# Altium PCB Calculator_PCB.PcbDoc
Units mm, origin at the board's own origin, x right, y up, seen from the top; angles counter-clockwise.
Board outline 55 x 114 mm, 2 copper layers (Top Layer, Bottom Layer); 61 components, 55 nets, 256 pads, 33 vias.
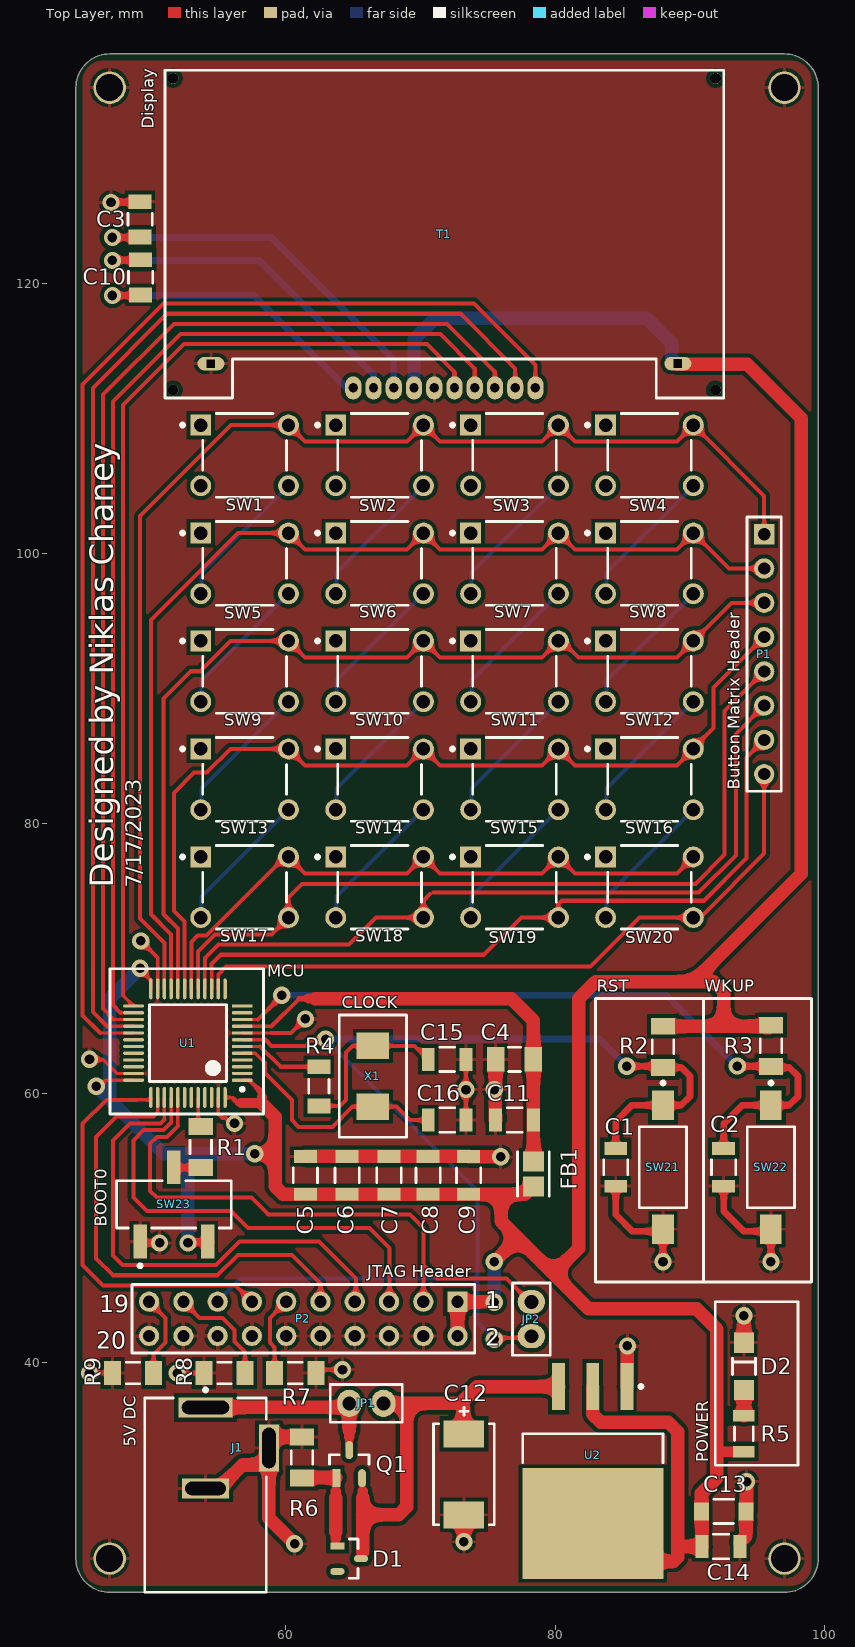
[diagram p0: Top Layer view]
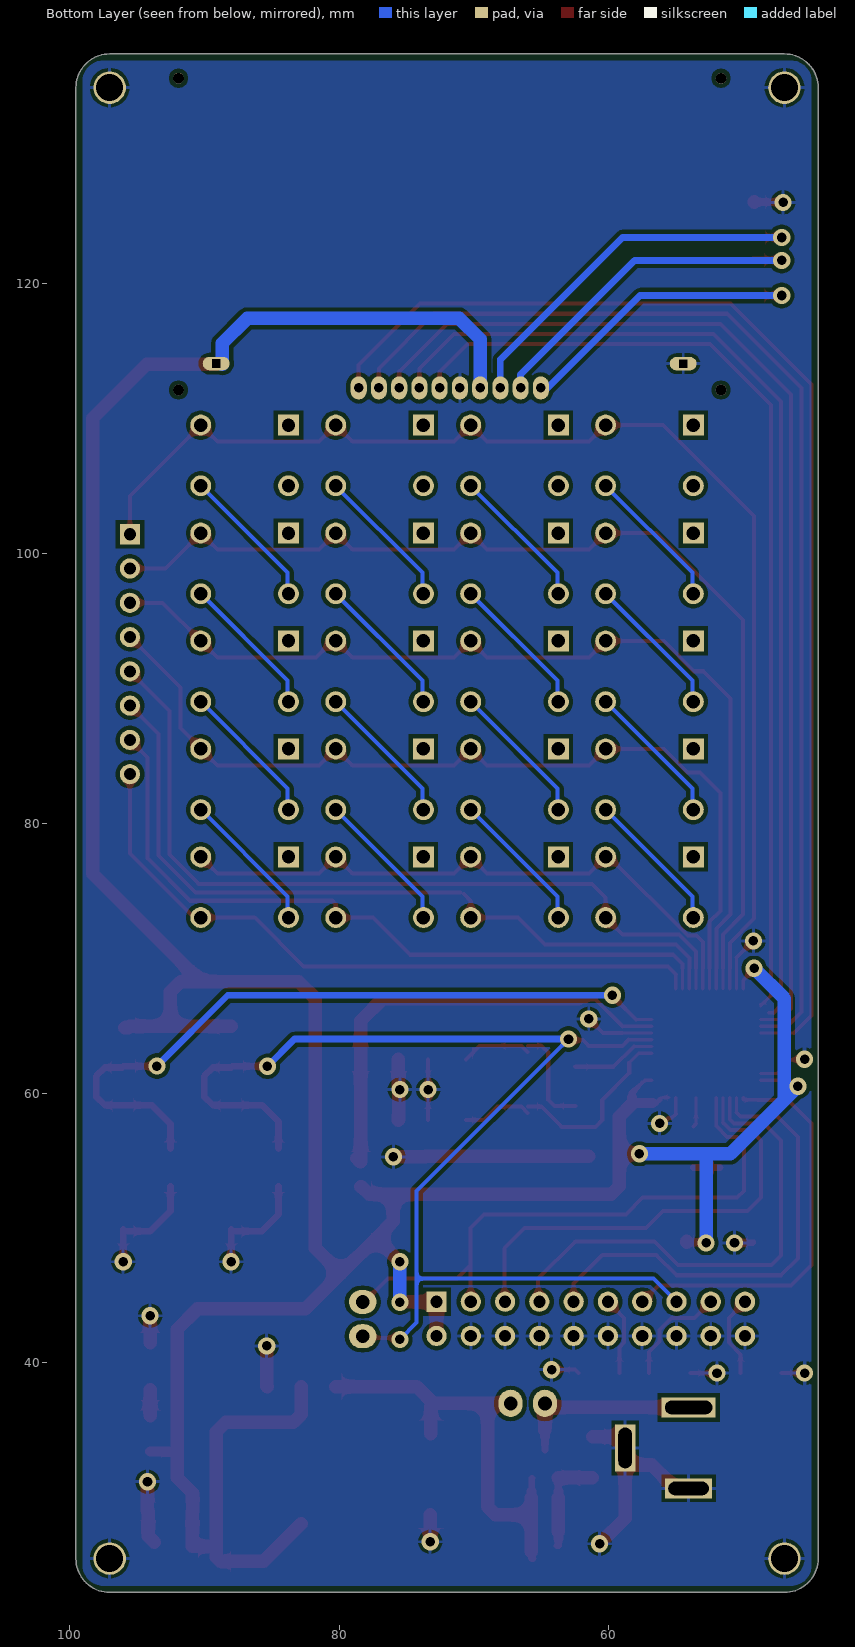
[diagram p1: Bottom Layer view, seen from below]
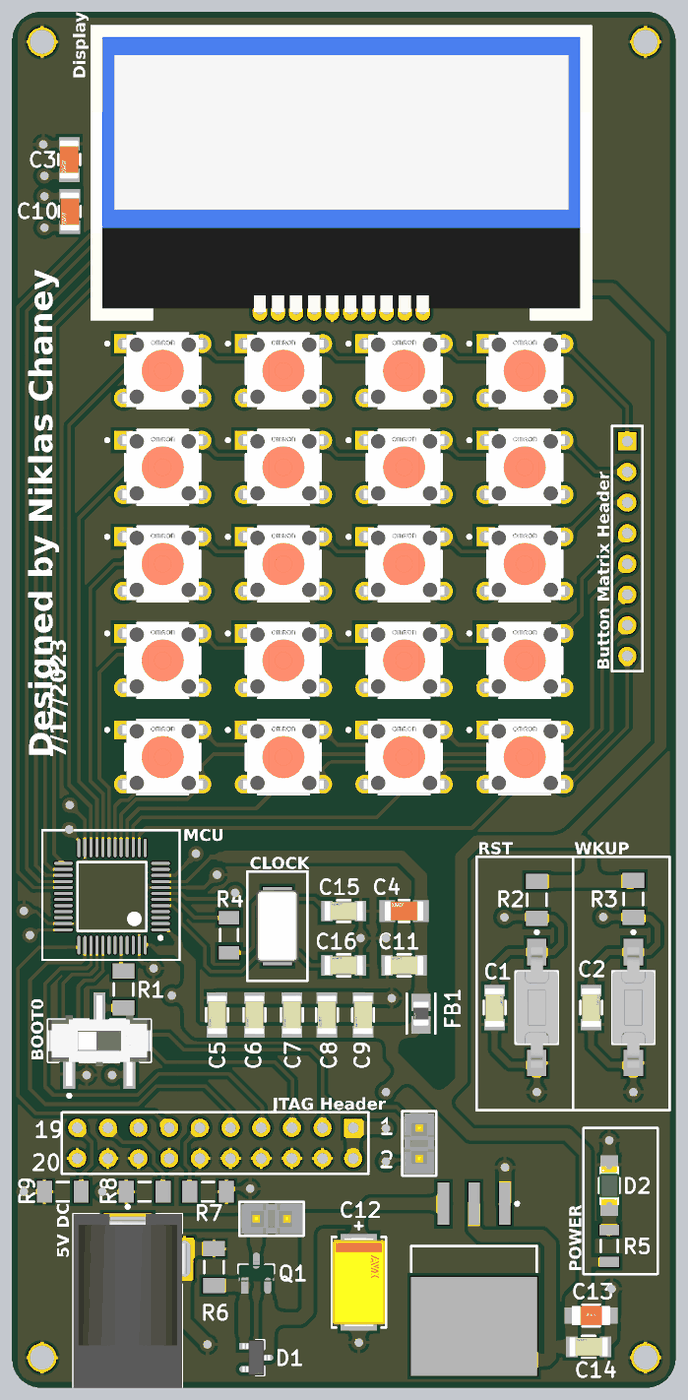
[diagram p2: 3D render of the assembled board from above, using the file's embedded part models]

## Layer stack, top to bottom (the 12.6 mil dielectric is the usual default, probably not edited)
Top Solder: solder mask 0.0102, Solder Resist, Dk 3.5
Top Layer: signal copper 0.0356
Dielectric 1: dielectric 0.32, FR-4, Dk 4.8
Bottom Layer: signal copper 0.0356
Bottom Solder: solder mask 0.0102, Solder Resist, Dk 3.5

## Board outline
44.5,25.5 ccw(c47,25.5) 47,23 97,23 ccw(c97,25.5) 99.5,25.5 99.5,134.5 ccw(c97,134.5) 97,137 47,137 ccw(c47,134.5) 44.5,134.5

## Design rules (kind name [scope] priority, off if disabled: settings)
Clearance [All] p1: gap=0.3 ignorepadtopadclearanceinfootprint=TRUE except(0.1: Arc-Arc Arc-Track Track-Track; 0.25: Arc-SMDPad Track-SMDPad)
HoleSize [All] p1: absolutevalues=TRUE maxlimit=5 minlimit=0.025 maxpercent=80.000 minpercent=20.000
MinimumSolderMaskSliver [All] p1: minsoldermaskwidth=0.046
PolygonConnect [All] p1: connectstyle=Relief reliefconductorwidth=0.254 reliefentries=4 polygonreliefangle="90 Angle" airgapwidth=0.254
RoutingVias [All] p1: holewidth=0.3 width=0.6 viastyle="Through Hole" minholewidth=0.3 minwidth=0.6 maxholewidth=0.3 maxwidth=0.6
SilkToSolderMaskClearance [IsPad] p1: minsilkscreentomaskgap=0.1 clearancetoexposedcopper=TRUE
SolderMaskExpansion [All] p1: expansion=0.102 istentingtop=FALSE
Width [All] p1: maxlimit=1 minlimit=0.25 preferedwidth=0.5
27 further rules are at their usual default settings.

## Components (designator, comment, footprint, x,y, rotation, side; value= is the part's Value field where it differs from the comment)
C1 "100nF" FP-C1206C-EB-MFG 84.5,54.5 r270 top value="0.10 μF"
C2 "100nF" FP-C1206C-EB-MFG 92.5,54.5 r270 top value="0.10 μF"
C3 "1uF" FP-1206-L_3_2_0_2-W_1_6_0-IPC_C 49.25,124.75 r270 top
C4 "10uF" FP-1206-L_3_2_0_2-W_1_6_0-IPC_B 77,62.5 r180 top
C5 "100nF" FP-C1206C-EB-MFG 61.5,53.9 r90 top value="0.10 μF"
C6 "100nF" FP-C1206C-EB-MFG 64.6,53.9 r90 top value="0.10 μF"
C7 "100nF" FP-C1206C-EB-MFG 67.7,53.9 r90 top value="0.10 μF"
C8 "100nF" FP-C1206C-EB-MFG 70.6,53.9 r90 top value="0.10 μF"
C9 "100nF" FP-C1206C-EB-MFG 73.6,53.9 r90 top value="0.10 μF"
C10 "1uF" FP-1206-L_3_2_0_2-W_1_6_0-IPC_C 49.3,120.449 r270 top
C11 "10nF" FP-C1206C-EB-MFG 77,58 r0 top value="10,000 pF"
C12 "220uF" FP-TAJE-MFG 73.25,31.75 r90 top
C13 "47uF" FP-C3216-160-0_2-MFG 92.5,29 r0 top
C14 "100nF" FP-C1206C-EB-MFG 92.3,26.4 r0 top value="0.10 μF"
C15 "20pF" FP-C1206C-EB-MFG 72,62.5 r0 top value="20 pF"
C16 "20pF" FP-C1206C-EB-MFG 72,58 r0 top value="20 pF"
D1 "BZX84-C15,215" FP-SOT23-IPC_C 64.75,25.5 r0 top
D2 "HSMG-C150" FP-HSMG-C150-MFG 94,39.75 r270 top
FB1 "BLM21AG121SN1D" FP-BLM21-0_2-t0_85-e0_5-IPC_A 78.4,54 r270 top
J1 "PJ-002A" CUI-PJ-002A_V 54.1,33.7 r270 top
JP1 "Jumper" "Jumper Small - 2.54 - GRAY" 66.02,37 r0 top
JP2 "Jumper" "Jumper Small - 2.54 - GRAY" 78.25,43.25 r270 top
P1 "Header 8" HDR1X8 95.5,101.41 r270 top
P2 "JTAG" HDR2X10 72.78,44.54 r180 top
Q1 "FDN360P" FP-527AG-IPC_B 64.75,32.5 r90 top
R1 "10K" RESC3116X65X40ML10T20 53.75,56 r270 top
R2 "10K" RESC3116X65X40ML10T20 88,63.425 r90 top
R3 "10K" RESC3116X65X40ML10T20 96,63.5 r90 top
R4 "390R" RESC3216X60X45NL10T20 62.5,60.5 r270 top
R5 "330R" RESC3116X65X40LL10T20 94,34.75 r90 top
R6 "10K" RESC3116X65X40ML10T20 61.25,33 r270 top
R7 "10K" RESC3116X65X40ML10T20 60.75,39.25 r180 top
R8 "10K" RESC3116X65X40ML10T20 55.5,39.25 r0 top
R9 "10K" RESC3116X65X40ML10T20 48.725,39.25 r0 top
SW1 "B3F-1055" FP-B3F-1055-MFG 57,107.25 r0 top
SW2 "B3F-1055" FP-B3F-1055-MFG 67,107.25 r0 top
SW3 "B3F-1055" FP-B3F-1055-MFG 77,107.25 r0 top
SW4 "B3F-1055" FP-B3F-1055-MFG 87,107.25 r0 top
SW5 "B3F-1055" FP-B3F-1055-MFG 57,99.25 r0 top
SW6 "B3F-1055" FP-B3F-1055-MFG 67,99.25 r0 top
SW7 "B3F-1055" FP-B3F-1055-MFG 77,99.25 r0 top
SW8 "B3F-1055" FP-B3F-1055-MFG 87,99.25 r0 top
SW9 "B3F-1055" FP-B3F-1055-MFG 57,91.25 r0 top
SW10 "B3F-1055" FP-B3F-1055-MFG 67,91.25 r0 top
SW11 "B3F-1055" FP-B3F-1055-MFG 77,91.25 r0 top
SW12 "B3F-1055" FP-B3F-1055-MFG 87,91.25 r0 top
SW13 "B3F-1055" FP-B3F-1055-MFG 57,83.25 r0 top
SW14 "B3F-1055" FP-B3F-1055-MFG 67,83.25 r0 top
SW15 "B3F-1055" FP-B3F-1055-MFG 77,83.25 r0 top
SW16 "B3F-1055" FP-B3F-1055-MFG 87,83.25 r0 top
SW17 "B3F-1055" FP-B3F-1055-MFG 57,75.25 r0 top
SW18 "B3F-1055" FP-B3F-1055-MFG 67,75.25 r0 top
SW19 "B3F-1055" FP-B3F-1055-MFG 77,75.25 r0 top
SW20 "B3F-1055" FP-B3F-1055-MFG 87,75.25 r0 top
SW21 "FSMSM" TECO-FSMSM-2_V 88,54.5 r270 top
SW22 "FSMSM" TECO-FSMSM-2_V 96,54.5 r270 top
SW23 "JS102011SCQN" FP-JS102011SCQN-MFG 51.75,51.75 r0 top
T1 "NHD-C0216CZ-NSW-BBW-3V3" NHD-C0216CZ-NSW-BBW-3V3 71.8,123.65 r0 top
U1 "STM32F103CBT6" STM-LQFP48_L 52.8,63.7 r180 top
U2 "LD1086D2M33TR" D2PAK_A_L 82.8,32 r270 top
X1 "ECS-160-20-23A-EN-TR" ECX-64AEN/64CEN 66.5,61.25 r90 top

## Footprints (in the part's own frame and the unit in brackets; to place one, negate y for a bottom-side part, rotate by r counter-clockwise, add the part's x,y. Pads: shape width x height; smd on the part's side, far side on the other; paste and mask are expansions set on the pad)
CUI-PJ-002A_V [mm] "THD, 3-Leads, Body 14.4x9mm, Height 11mm"
  rect 1.5x4 hole 1 slot 3.5 at 90 deg: 1(-3,0)
  rect 1.5x3.5 hole 1 slot 3 at 90 deg: 2(3,0)
  rect 3.5x1.5 hole 1 slot 3 at 0 deg: 3(0,4.7)
  silkscreen extent -4.42,-4.5 10.7,4.5, body extent -3.7,-4.5 10.7,4.9, height 11
D2PAK_A_L [mm] "D2-PAK, 4-Leads, Body 9.2x10.2mm, Pitch 2.54mm, Lead Span 15.4mm, IPC High Density"
  rect 3.5x0.95 smd: 1(-6.25,2.54) 2(-6.25,0) 3(-6.25,-2.54)
  rect 8.2x10.45 smd: 4(3.9,0)
  silkscreen extent -6.37,-5.2 -0.6,5.2, body extent -2.75,-5.2 6.6,5.2, height 4.6
ECX-64AEN/64CEN [mm]
  rect 1.96x2.4 smd: 1(-2.25,0) 2(2.25,0)
  silkscreen extent -4.53,-2.5 4.53,2.5, body extent -3,-1.75 3,1.75, height 1.11
FP-527AG-IPC_B [mm]
  rect 1.336x0.585 smd paste+0 mask+0: 1(-1.04,0.95)
  rrect100% 1.336x0.585 smd paste+0 mask+0: 2(-1.04,-0.95) 3(1.04,0)
  silkscreen extent 0,-1.46 0.7,1.46, body extent -1.96,-1.71 1.96,1.71, height 0.25
FP-1206-L_3_2_0_2-W_1_6_0-IPC_B [mm]
  rect 1.305x1.806 smd paste+0 mask+0: 1(-1.401,0) 2(1.401,0)
  silkscreen extent -0.45,-0.9 0.45,0.9, body extent -2.3,-1.15 2.3,1.15, height 0.25
FP-1206-L_3_2_0_2-W_1_6_0-IPC_C [mm]
  rect 1.105x1.706 smd paste+0 mask+0: 1(-1.301,0) 2(1.301,0)
  silkscreen extent -0.45,-0.9 0.45,0.9, body extent -1.95,-1 1.95,1, height 0.25
FP-B3F-1055-MFG [mm]
  rect 1.55x1.55 hole 1 paste-1000 mask+0: 1(-3.25,2.25)
  round 1.55 hole 1 paste-1000 mask+0: 2(3.25,2.25) 3(-3.25,-2.25) 4(3.25,-2.25)
  silkscreen extent -4.72,-3.1 3.1,3.1, body extent -4.13,-3.2 4.13,3.2, height 0.25
FP-BLM21-0_2-t0_85-e0_5-IPC_A [mm]
  rect 1.455x1.556 smd paste+0 mask+0: 1(-0.926,0) 2(0.926,0)
  silkscreen extent -1.65,-1.18 1.65,1.18, body extent -2.15,-1.28 2.15,1.28, height 0.25
FP-C1206C-EB-MFG [mm]
  rect 0.95x1.7 smd paste+0 mask+0: 1(-1.4,0) 2(1.4,0)
  silkscreen extent -0.55,-0.9 0.55,0.9, body extent -2,-1 2,1, height 0.25
FP-C3216-160-0_2-MFG [mm]
  rect 1.1x1.35 smd paste+0 mask+0: 1(-1.65,0) 2(1.65,0)
  silkscreen extent -0.72,-0.9 0.72,0.9, body extent -2.3,-1 2.3,1, height 0.25
FP-HSMG-C150-MFG [mm]
  rect 1.5x1.5 smd paste+0 mask+0: 1(-1.75,0) 2(1.75,0)
  silkscreen extent -0.6,-0.85 0.6,0.85, body extent -2.6,-0.95 2.6,0.95, height 0.25
FP-JS102011SCQN-MFG [mm]
  rect 1x2.5 smd paste+0 mask+0: 1(-2.5,-2.75) 2(0,2.75) 3(2.5,-2.75)
  silkscreen extent -4.25,-4.67 4.25,1.75, body extent -4.35,-4.1 4.35,4.1, height 0.25
FP-SOT23-IPC_C [mm]
  rect 1.055x0.522 smd paste+0 mask+0: 1(-0.875,0.95)
  rrect100% 1.055x0.522 smd paste+0 mask+0: 2(-0.875,-0.95) 3(0.875,0)
  silkscreen extent 0,-1.45 0.65,1.45, body extent -1.5,-1.55 1.5,1.55, height 0.25
FP-TAJE-MFG [mm]
  rect 2x3 smd paste+0 mask+0: 1(-3,0) 2(3,0)
  silkscreen extent -3.75,-2.25 4.97,2.25, body extent -4.1,-2.35 4.1,2.35, height 0.25
HDR1X8 [mm] "Connector; Header; 8 Position"
  rect 1.5x1.5 hole 0.9: 1(0,0)
  round 1.5 hole 0.9: 2(2.54,0) 3(5.08,0) 4(7.62,0) 5(10.16,0) 6(12.7,0) 7(15.24,0) 8(17.78,0)
  silkscreen extent -1.27,-1.27 19.05,1.27
HDR2X10 [mm] "Connector; Header; 10x2 Position"
  rect 1.5x1.5 hole 0.9: 1(0,0)
  round 1.5 hole 0.9: 2(0,2.54) 3(2.54,0) 4(2.54,2.54) 5(5.08,0) 6(5.08,2.54) 7(7.62,0) 8(7.62,2.54) 9(10.16,0) 10(10.16,2.54) 11(12.7,0) 12(12.7,2.54) 13(15.24,0) 14(15.24,2.54) 15(17.78,0) 16(17.78,2.54) 17(20.32,0) 18(20.32,2.54) 19(22.86,0) 20(22.86,2.54)
  silkscreen extent -1.27,-1.27 24.13,3.81
"Jumper Small - 2.54 - GRAY" [mil]
  oval 70x80 hole 40: 1(-50,0) 2(50,0)
  silkscreen extent -105,-55 105,55, body extent -100,-50 100,50, height 337
NHD-C0216CZ-NSW-BBW-3V3 [mm]
  rrect100% 1.2x1.7 hole 0.7: 1(6.75,-11.4) 2(5.25,-11.4) 3(3.75,-11.4) 4(2.25,-11.4) 5(0.75,-11.4) 6(-0.75,-11.4) 7(-2.25,-11.4) 8(-3.75,-11.4) 9(-5.25,-11.4) 10(-6.75,-11.4)
  oval 2x1 hole 0.6 square: A(17.304,-9.59) K(-17.3,-9.6)
  round 0.8 hole 0.8 unplated: TH(-20.1,-11.55) TH(-20.1,11.55) TH(20.1,-11.55) TH(20.1,11.55)
  silkscreen extent -20.7,-12.15 20.7,12.15, body extent -20.7,-12.15 20.7,12.15, height 4.1
RESC3116X65X40LL10T20 [mm] "Chip Resistor, 2-Leads, Body 3.10x1.60mm, IPC High Density"
  rect 0.85x1.6 smd: 1(-1.325,0) 2(1.325,0)
  silkscreen extent -0.5,-0.7 0.5,0.7, body extent -1.6,-0.85 1.6,0.85, height 0.65
RESC3116X65X40ML10T20 [mm] "Chip Resistor, 2-Leads, Body 3.10x1.60mm, IPC Low Density"
  rect 1.25x1.8 smd: 1(-1.525,0) 2(1.525,0)
  silkscreen extent -0.5,-0.8 0.5,0.8, body extent -1.6,-0.85 1.6,0.85, height 0.65
RESC3216X60X45NL10T20 [mm] "Chip Resistor, 2-Leads, Body 3.20x1.60mm, IPC Medium Density"
  rect 1.1x1.7 smd: 1(-1.45,0) 2(1.45,0)
  silkscreen extent -0.5,-0.75 0.5,0.75, body extent -1.65,-0.85 1.65,0.85, height 0.6
STM-LQFP48_L [mm] "QFP, 48-Leads, Body 7x7mm, Pitch 0.5mm, IPC High Density"
  oval 1.55x0.25 smd: 1(-4.025,2.75) 2(-4.025,2.25) 3(-4.025,1.75) 4(-4.025,1.25) 5(-4.025,0.75) 6(-4.025,0.25) 7(-4.025,-0.25) 8(-4.025,-0.75) 9(-4.025,-1.25) 10(-4.025,-1.75) 11(-4.025,-2.25) 12(-4.025,-2.75) 25(4.025,-2.75) 26(4.025,-2.25) 27(4.025,-1.75) 28(4.025,-1.25) 29(4.025,-0.75) 30(4.025,-0.25) 31(4.025,0.25) 32(4.025,0.75) 33(4.025,1.25) 34(4.025,1.75) 35(4.025,2.25) 36(4.025,2.75)
  oval 0.25x1.55 smd: 13(-2.75,-4.025) 14(-2.25,-4.025) 15(-1.75,-4.025) 16(-1.25,-4.025) 17(-0.75,-4.025) 18(-0.25,-4.025) 19(0.25,-4.025) 20(0.75,-4.025) 21(1.25,-4.025) 22(1.75,-4.025) 23(2.25,-4.025) 24(2.75,-4.025) 37(2.75,4.025) 38(2.25,4.025) 39(1.75,4.025) 40(1.25,4.025) 41(0.75,4.025) 42(0.25,4.025) 43(-0.25,4.025) 44(-0.75,4.025) 45(-1.25,4.025) 46(-1.75,4.025) 47(-2.25,4.025) 48(-2.75,4.025)
  silkscreen extent -4.15,-2.85 2.85,3.55, body extent -3.5,-3.5 3.5,3.5, height 1.6
TECO-FSMSM-2_V [mm] "SMD, 2-Leads, Body 6x3.5mm, Pitch 9.19mm"
  rect 2.2x1.6 smd: 1(-4.595,0)
  rect 2.18x1.6 smd: 2(4.595,0)
  silkscreen extent -6.37,-1.75 3,1.75, body extent -4.98,-1.75 4.98,1.75, height 4.4

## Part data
C1 C2 C5 C6 C7 C8 C9 C14: library part CMP-03020-021070-1, "CAP CER 0.1UF 16V 10% X7R 1206", Capacitance="0.10 μF", Manufacturer=KEMET, Manufacturer Part Number=C1206C104K4RACTU, Package=C1206C-EB, Temperature="-55°C to +150°C", Temperature Characteristic=X7R, Temperature Coefficient=15%, Temperature Range High=+150°C, Temperature Range Low=-55°C, Tolerance=0.1, Voltage Rating="16 V"
C3 C10: library part CMP-04427-011211-1, "General Purpose Ceramic Capacitor, 1206, 1uF, 20%, X7R, 15%, 16V", Case Code (Imperial)=1206, Case Code (Metric)=3216, Dielectric=X7R, Max Operating Temperature=125°C, Min Operating Temperature=-55°C, Package Quantity=1, Tolerance=20%, Voltage Rating=16V
C4: library part CMP-04427-000082-1, "General Purpose Ceramic Capacitor, 1206, 10uF, 10%, X5R, 15%, 16V", Case Code (Imperial)=1206, Case Code (Metric)=3216, Dielectric=X5R, Max Operating Temperature=85°C, Min Operating Temperature=-55°C, Package Quantity=1, Tolerance=10%, Voltage=16V
C11: library part CMP-1037-03529-2, "CAP CER 10000PF 200V X7R 1206", Capacitance="10,000 pF", Manufacturer=KEMET, Manufacturer Part Number=C1206C103K2RACTU, Package=C1206C-EB, Temperature="-55°C to +150°C", Temperature Characteristic=X7R, Temperature Coefficient=15%, Temperature Range High=+150°C, Temperature Range Low=-55°C, Tolerance=0.1, Voltage Rating="200 V"
C12: library part CMP-04424-000272-1, "220uF 16V  ±20% 500mΩ 2917  SMD Tantalum Capacitor", Case Code (Imperial)=2917, Case Code (Metric)=7343, ESR (Equivalent Series Resistance)=500mR, Leakage Current=35.2uA, Max Operating Temperature=125°C, Min Operating Temperature=-55°C, Package Quantity=1, Tolerance=20%, Voltage Rating=16V
C13: library part CMP-2000-07442-2, "Multilayer Ceramic Capacitors 47uF ±20% 16V X5R SMD 1206", Case Code (Imperial)=1206, Case Code (Metric)=3216, Dielectric=X5R, Dielectric Material=Ceramic, Max Operating Temperature=85°C, Min Operating Temperature=-55°C, Package Quantity=1, Tolerance=20%, Voltage Rating=16V
C15 C16: library part CMP-1037-00940-2, "1206 C 20pF Ceramic Multilayer Capacitor; 50 VDC; +125degC; C0G Dielec; +/-5%", Capacitance="20 pF", Manufacturer=KEMET, Manufacturer Part Number=C1206C200J5GACTU, Package=C1206C-EB, Temperature="-55°C to +150°C", Temperature Characteristic=C0G, Temperature Coefficient=15%, Temperature Range High=+150°C, Temperature Range Low=-55°C, Tolerance=0.05, Voltage Rating="50 V"
D1: library part CMP-14400-000028-1, "DIODE ZENER 15V 250MW TO236AB"
D2: library part CMP-2000-05061-2, "LED GREEN DIFFUSED 1206 SMD", Colour=Green, Forward Current=20mA, Forward Voltage=2.2V, Manufacturer=Broadcom, Max Junction Temp=+95°C, Power Dissipation=65mW, Reverse Voltage=5V, Temperature="-40°C to +85°C", Temperature Range High=+85°C, Temperature Range Low=-40°C
FB1: library part CMP-0686-00716-3, "FERRITE BEAD 120 OHM 0805 1LN", Case Code (Imperial)=0805, Case Code (Metric)=2012, Current Rating=800mA, DC Current=200mA, DC Resistance (DCR)=100mR, Frequency=100MHz, Max Current Rating=1A, Max Operating Temperature=125°C, Min Operating Temperature=-55°C, Package Quantity=1, Resistance=150mR, Tolerance=25%
J1: library part CMP-2000-06895-2, "Through Hole Right Angle DC Power Jack, 2.5 A, 2 mm Center Pin, 3 Position, -25 to 85 degC, RoHS, Bulk", Current Rating=2.5A, Flammability Rating=UL94V-0, Insulation Resistance=50MOhms, Manufacturer=CUIInc., Operating Temperature Range=-25Cto+85C, Package Description="3-Pin Through Hole Device, Body 14.4 x 9 mm, Height 11 mm", Voltage Rating=24V
P1: "Header, 8-Pin"
P2: library part "Header 10X2", "Header, 10-Pin, Dual row"
Q1: library part CMP-2000-07455-3, "MOSFET P-CH 30V 2A SSOT3", Case/Package=SOT-23, Continuous Drain Current (ID)=2A, Current Rating=-2A, Drain to Source Breakdown Voltage=-30V, Drain to Source Resistance=63mR, Drain to Source Voltage (Vdss)=30V, Gate to Source Voltage (Vgs)=20V, Input Capacitance=298pF, Max Operating Temperature=150°C, Max Power Dissipation=500mW, Min Operating Temperature=-55°C, On-State Resistance=80MR, Package Quantity=1
R1 R2 R3 R6 R7 R8 R9: library part CMP-1014-00623-2, "Chip Resistor, 10 KOhm, +/- 1%, 0.25 W, -55 to 155 degC, 1206 (3216 Metric), RoHS, Tape and Reel", Case Code (Imperial)=1206, Case Code (Metric)=3216, Manufacturer=Yageo, Max Operating Temperature=155degC, Min Operating Temperature=-55degC, Package Description="2-Pin Surface Mount Device, Body 3.1 x 1.6 mm", Package Quantity=5000, Package Reference=1206.0, Power Rating=250mW, Resistance=10KOhm, Temperature Coefficient=100ppm/degreesC, Tolerance=1%, Voltage Rating=200V
R4: library part CMP-2003-02135-1, Manufacturer="Vishay Dale", Part Number=CRCW1206390RJNEA
R5: library part CMP-2000-06969-1, "Chip Resistor, 330 Ohm, +/- 1%, 250 mW, -55 to 155 degC, 1206 (3216 Metric), RoHS, Tape and Reel", Case Code - in=1206, Case Code - mm=3216, Manufacturer=Yageo, Operating Temperature Range=-55Cto+155C, Package Description="2-Pin Surface Mount Device, Body 3.1 x 1.6 mm", Power Rating=250mW(1/4W), Resistance=330Ohms, Temperature Coefficient=100PPM/C, Tolerance=1%, Voltage Rating=200V
SW1 SW2 SW3 SW4 SW5 SW6 SW7 SW8 SW9 SW10 SW11 SW12 SW13 SW14 SW15 SW16 SW17 SW18 SW19 SW20: library part CMP-08834-000061-1, "SWITCH TACTILE SPST-NO 0.05A 24V", Actuator Color=Orange, Contact Current Rating=50mA, Contact Resistance=100mR, Max Operating Temperature=70°C, Max Voltage Rating (DC)=24V, Min Operating Temperature=-25°C, Operating Force=2.55N, Package Quantity=1500, Supplier Part Number=SW795-ND
SW21 SW22: library part CMP-2000-07511-1, "FSMSM Push Button Switch, 50 mA, -35 to 85 degC, 2-Pin SMD, RoHS, Bulk", Case\/Package=SMD/SMT, Contact Current Rating=50mA, Contact Resistance=100mOhm, Manufacturer="TE Connectivity", Max Operating Temperature=85degC, Max Voltage Rating (DC)=12V, Min Operating Temperature=-35degC, Operating Force=180gf, Package Description="2-Pin Surface Mount Device, Body 6 x 3.5 mm, Pitch 9.19 mm", Package Quantity=1000, Voltage Rating (DC)=24V
SW23: library part CMP-10038-000023-1, "SWITCH SLIDE SPDT 300MA 6V", Actuator Color=Black, Case/Package=SMD/SMT, Contact Resistance=70mR, Current Rating=300mA, Max Operating Temperature=85°C, Max Voltage Rating (DC)=30V, Min Operating Temperature=-40°C, Package Quantity=4000, Voltage Rating (DC)=6V
T1: "LCD MOD 32DIG 16X2 TRANSMISV WHT", Supplier Part Number 1=NHD-C0216CZ-NSW-BBW-3V3-ND
U1: library part CMP-0237-00250-3, "ARM Cortex-M3 32-bit MCU, 128 KB Flash, 20 KB Internal RAM, 37 I/Os, 48-pin LQFP, -40 to 85 degC, Tray", I/Os (High Current)=37, Operating Frequency(F) (Processor speed) (MHz)=72, Supply Voltage(Vcc) min (V)=2
U2: library part CMP-0244-00505-1, "1.5A, Low Drop Positive Voltage Regulator, 3.3V, 4-Pin D2PAK/A, Tape and Reel"
X1: "CRYSTAL 16.0000MHZ 20PF SMD", Supplier Part Number 1=54AK5822

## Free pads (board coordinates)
  round 2.4 hole 2: MH(47,25.5) MH(47,134.5) MH(97,25.5) MH(97,134.5)

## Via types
v1: diameter 1.27, hole 0.711, Top Layer to Bottom Layer, tented both sides, 33 vias

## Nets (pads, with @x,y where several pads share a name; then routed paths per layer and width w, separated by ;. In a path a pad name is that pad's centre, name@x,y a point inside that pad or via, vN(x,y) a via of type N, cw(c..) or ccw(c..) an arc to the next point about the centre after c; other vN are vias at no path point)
+3V3: C5.1 C6.1 C7.1 C8.1 C9.1 C13.1 C14.1 FB1.2 P2.1 P2.2 R2.2 R3.2 R5.1 SW23.3 T1.7 T1.A U1.1 U1.24 U1.36 U1.48 U2.2 U2.4 | length 274
  Top Layer w0.25: v1(46,60.5) 46.276,60.5 46.726,60.95 U1.36 ; v1(49.25,69.25) 49.25,69.175 50.05,68.375 U1.24 ; U1.48 56.075,59.675 56.25,59.5 ; U1.1 57.35,60.95 57.9,60.4
  Top Layer w0.4: 56.25,59.5 56.5,59.25 56.75,59.25 ; 57.9,60.4 58.1,60.2
  Top Layer w0.5: v1@52.85,48.95 SW23.3@54.25,48.95 ; 58.1,60.2 58.3,60 58.3,59.7 ; R2.2 R2.2@88.112,64.838 ; R3.2@95.887,65.137 R3.2
  Top Layer w0.75: 56.75,59.25 58.25,59.25 58.3,59.2 58.3,59.7 ; 92.075,33.425 R5.1
  Top Layer w1: v1(52.8,48.9) v1@52.85,48.95 ; SW23.3@54.25,48.95 SW23.3 ; v1(57.75,55.5) 59.25,55.5 ; 58.3,59.2 59.25,58.25 59.25,55.5 ; P2.2 P2.1 72.8,44.52 75.48,44.52 v1(75.5,44.5) ; v1(75.5,47.5) 77.25,49.25 ; FB1.2 78.349,53.074 77.775,52.5 76,52.5 ; U2.4 85.6,25.3 88.8,25.3 89.1,25.6 89.1,26.4 89.1,34.9 88.4,35.6 83.386,35.6 82.8,36.186 U2.2 ; R2.2 92.5,64.95 ; T1.A@89.104,114 94.25,114 98.25,110 98.25,107.5 98.25,76.25 90.25,68.25 ; 89.2,26.4 C14.1 90.875,26.425 90.875,28.975 C13.1 90.85,30.35 92,31.5 92,33.5 ; 92.075,33.425 92,33.5 ; R3.2@95.887,64.838 95.612,64.838 95.5,64.95 92.5,64.95 ; 59.25,55.5 59.25,53.086 59.836,52.5 C5.1 C6.1 C7.1 C8.1 C9.1 76,52.5 ; 76,52.5 76,50.5 77.25,49.25 ; 77.25,49.25 79.875,46.625 ; 79.875,46.625 82.5,44 90.5,44 92,42.5 92,33.5 ; 79.875,46.625 81.75,48.5 81.75,67 83,68.25 90.25,68.25 ; 90.25,68.25 91.75,68.25 92.5,67.5 92.5,64.95
  Bottom Layer w1: v1(46,60.5) 47,59.5 ; v1(49.25,69.25) 47,67 47,59.5 ; v1(52.8,48.9) 52.8,55.45 52.75,55.5 ; v1(57.75,55.5) 52.75,55.5 ; T1.7 69.55,115.85 71.1,117.4 86.814,117.4 88.654,115.56 T1.A@88.654,114 ; v1(75.5,44.5) v1(75.5,47.5) ; 47,59.5 51,55.5 52.75,55.5
BOOT0_SW: R1.2 SW23.2 | length 2
  Top Layer w0.3: SW23.2 SW23.2@51.775,54.475
  Top Layer w0.5: SW23.2@51.775,54.475 R1.2
CL+: C10.1 T1.9 | length 26
  Top Layer w0.5: v1(47.2,121.7) 47.225,121.725 49.275,121.725 C10.1
  Bottom Layer w0.5: v1(47.2,121.7) 58.1,121.7 66.55,113.25 T1.9
CL-: C10.2 T1.10 | length 22.8
  Top Layer w0.3: C10.2@49.252,119.1 C10.2
  Top Layer w0.5: v1(47.2,119.1) C10.2@49.252,119.1
  Bottom Layer w0.5: v1(47.2,119.1) 57.7,119.1 64.55,112.25 T1.10
GND: C1.2 C2.2 C3.1 C4.2 C5.2 C6.2 C7.2 C8.2 C9.2 C11.1 C12.1 C13.2 C14.2 C15.2 C16.2 D2.1 J1.2 J1.3 P2.4 P2.6 P2.8 P2.10 P2.12 P2.14 P2.16 P2.18 P2.20 pad.MH R6.1 R7.1 R8.1 R9.1 SW21.2 SW22.2 SW23.1 T1.6 T1.K U1.8 U1.23 U1.35 U1.47 U2.1 | length 94.3
  Top Layer w0.25: v1(45.5,62.5) 45.531,62.469 46.51,62.469 47.529,61.45 U1.35 ; U1.23 50.55,70.027 ; 55.05,58.45 U1.47 ; U1.8 59,64.45
  Top Layer w0.3: v1(45.5,39.25) R9.1 ; SW23.1 SW23.1@49.35,48.9 ; v1(49.301,71.276) 50.55,70.027 ; v1(52,39.25) R8.1 ; 55.05,58.45 55.352,58.148 55.59,58.148 55.988,57.75 v1(56.25,57.75) ; 59,64.45 60.45,64.45 v1(61.5,65.5) ; R7.1 62.525,39.5 v1(64.25,39.5) ; C16.2 C15.2
  Top Layer w0.5: v1@47.125,126.025 C3.1@49.225,126.025 ; SW23.1@49.35,48.9 v1(50.7,48.9) ; C1.2 84.5,51 85.75,49.75 87.845,49.75 SW21.2 v1(88,47.5) ; C2.2 92.5,51.25 94,49.75 95.845,49.75 SW22.2 v1(96,47.5) ; v1(94.2,31.2) v1@94.2,31.4
  Top Layer w1: v1(47.1,126) v1@47.125,126.025 ; C3.1@49.225,126.025 C3.1 ; J1.2 55.1,30.7 56.85,32.45 58.55,32.45 J1.3@58.8,32.7 ; v1(60.7,26.6) 58.8,28.5 J1.3@58.8,32.7 ; R6.1@61.2,34.525 59.05,34.525 58.8,34.275 J1.3 J1.3@58.8,32.7 ; C5.2 C6.2 C7.2 C8.2 C9.2 73.625,55.275 v1(75.975,55.275) v1@76,55.25 ; v1(73.25,26.75) C12.1 ; C4.2 75.599,60.422 75.5,60.323 v1(75.5,60.25) 75.5,60.177 75.575,60.102 75.575,58.025 C11.1 C11.1@75.6,58.325 ; U2.1 85.365,38.275 v1(85.365,41.265) ; C14.2@93.7,26.725 94.15,27.175 C13.2 ; D2.1 v1(94,43.5) ; C13.2@94.2,29.05 v1(94.2,31.2)
  other v1: 73.4,60.25
MCU-NRST: C1.1 JP2.2 P2.15 R2.1 SW21.1 U1.7 | length 94.7
  Top Layer w0.25: U1.7 58.55,63.95
  Top Layer w0.3: 58.55,63.95 59,63.5 61.5,63.5 61.915,63.915 62.915,63.915 v1(63,64) ; v1(75.5,41.75) 75.615,41.865 78.135,41.865 JP2.2
  Top Layer w0.5: C1.1 84.5,57.9 85.7,59.1 87.995,59.1 SW21.1 89.345,59.095 90,59.75 90,61.25 89.357,61.893 88.007,61.893 87.915,61.985 v1(85.315,61.985)
  Bottom Layer w0.3: P2.15 56.71,46.25 74.25,46.25 ; v1(63,64) 74.25,52.75 74.25,46.25 ; v1(75.5,41.75) 74.25,43 74.25,46.25
  Bottom Layer w0.5: v1(63,64) 83.3,64 v1(85.315,61.985)
MCU-OSC_IN: C16.1 U1.5 X1.1 | length 18.6
  Top Layer w0.25: U1.5 57.8,62.95 58.5,62.25
  Top Layer w0.3: 58.5,62.25 58.5,61.5 60.5,59.5 60.5,58 61,57.5 63.5,57.5 65,59 X1.1@66,59 ; X1.1@66.026,58.526 X1.1 68.25,59 69.25,58 C16.1
MCU-OSC_OUT': R4.1 U1.6 | length 6.3
  Top Layer w0.25: U1.6 58.15,63.45
  Top Layer w0.3: 58.15,63.45 59.65,61.95 R4.1
MCU-PA4_C4: P1.5 SW17.4 U1.17 | length 60.4
  Top Layer w0.25: U1.17 53.55,69.25
  Top Layer w0.3: 53.55,69.25 53.55,70.5 54.8,71.75 59,71.75 SW17.4 60.25,74.5 61.25,75.5 90.4,75.5 92.575,77.675 92.575,88.325 94,89.75 P1.5
MCU-PA5_C3: P1.6 SW18.4 U1.16 | length 57.2
  Top Layer w0.25: U1.16 54.05,69.25
  Top Layer w0.3: 54.05,69.25 54.05,70 55.05,71 64.75,71 66.75,73 SW18.4 70.25,74.25 70.75,74.75 ; 71.002,74.85 90.65,74.85 93.4,77.6 93.4,86.61 P1.6
MCU-PA6_C2: P1.7 SW19.4 U1.15 | length 54.6
  Top Layer w0.25: U1.15 54.55,69.25
  Top Layer w0.3: 54.55,69.25 54.55,69.55 55.25,70.25 74.75,70.25 77.5,73 SW19.4 80.25,74 80.5,74.25 91.05,74.25 94.2,77.4 94.2,84.87 P1.7
MCU-PA7_C1: P1.8 SW20.4 U1.14 | length 51.1
  Top Layer w0.25: U1.14 55.05,68.8
  Top Layer w0.3: 55.05,68.8 55.625,69.375 82.625,69.375 86.25,73 SW20.4 90.489,73.239 90.989,73.239 95.5,77.75 P1.8
MCU-PA8_R1: P1.1 SW1.2 SW2.2 SW3.2 SW4.2 U1.22 | length 92.9
  Top Layer w0.25: U1.22 51.05,69.25
  Top Layer w0.3: 51.05,69.25 51.05,71.134 49.25,72.934 49.25,102.75 56,109.5 SW1.2 61.475,108.275 69.025,108.275 SW2.2 71.475,108.275 79.025,108.275 SW3.2 81.475,108.275 89.025,108.275 SW4.2 95.5,104.25 P1.1
MCU-PA9_R2: P1.2 SW5.2 SW6.2 SW7.2 SW8.2 U1.21 | length 80.2
  Top Layer w0.25: U1.21 51.55,69.25
  Top Layer w0.3: 51.55,69.25 51.55,71.763 50.063,73.25 50.063,95.045 56.518,101.5 SW5.2 61.475,100.275 69.025,100.275 SW6.2 71.475,100.275 79.025,100.275 SW7.2 81.475,100.275 89.025,100.275 SW8.2 92.88,98.87 P1.2
MCU-PA10_R3: P1.3 SW9.2 SW10.2 SW11.2 SW12.2 U1.20 | length 72.4
  Top Layer w0.25: U1.20 52.05,69.25
  Top Layer w0.3: 52.05,69.25 52.05,72.2 51,73.25 51,89.25 53.005,91.255 53.692,91.255 55.936,93.5 SW9.2 61.475,92.275 69.025,92.275 SW10.2 71.475,92.275 79.025,92.275 SW11.2 80.5,93.5 81.725,92.275 89.025,92.275 SW12.2 93.08,96.33 P1.3
MCU-PA11_R4: P1.4 SW13.2 SW14.2 SW15.2 SW16.2 U1.19 | length 68.2
  Top Layer w0.25: U1.19 52.55,69.25
  Top Layer w0.3: 52.55,69.25 52.55,72.7 51.75,73.5 51.75,82.25 53.255,83.755 54.192,83.755 55.936,85.5 SW13.2 61.475,84.275 69.025,84.275 SW14.2 71.475,84.275 79.025,84.275 SW15.2 81.475,84.275 89.025,84.275 SW16.2 90.25,85.566 91.75,87.066 91.75,90.04 P1.4
MCU-PA12_R5: SW17.2 SW18.2 SW19.2 SW20.2 U1.18 | length 46.3
  Top Layer w0.25: U1.18 53.05,69.25
  Top Layer w0.3: 53.05,69.25 53.05,71.2 53.525,71.675 54.157,71.675 59.982,77.5 SW17.2 61.475,76.275 69.025,76.275 SW18.2 71.475,76.275 79.025,76.275 SW19.2 81.475,76.275 89.025,76.275 SW20.2
MCU-PB0_RST: T1.1 U1.29 | length 90.7
  Top Layer w0.25: 46.3,64.45 U1.29
  Top Layer w0.3: 46.3,64.45 45,65.75 45,112.5 51,118.5 74,118.5 78.55,113.95 T1.1
MCU-PB1_RS: T1.2 U1.28 | length 86.4
  Top Layer w0.25: 46.8,64.95 U1.28
  Top Layer w0.3: 46.8,64.95 45.75,66 45.75,112.25 51.25,117.75 73,117.75 77.05,113.7 T1.2
MCU-PB2_CSB: T1.3 U1.27 | length 82
  Top Layer w0.25: 47.3,65.45 U1.27
  Top Layer w0.3: 47.3,65.45 46.5,66.25 46.5,111.75 51.75,117 72,117 75.55,113.45 T1.3
MCU-PB3_SCL: T1.4 U1.26 | length 77.2
  Top Layer w0.25: 47.812,65.95 U1.26@48.15,65.95
  Top Layer w0.3: 47.812,65.95 47.25,66.512 47.25,111.25 52.25,116.25 71.5,116.25 74.05,113.7 T1.4
MCU-PB4_SI: T1.5 U1.25 | length 73.3
  Top Layer w0.25: 48,67.225 U1.25
  Top Layer w0.3: 48,67.225 48,111 52.5,115.5 70.5,115.5 72.55,113.45 T1.5
MCU-VDDA: C4.1 C11.2 FB1.1 U1.9 | length 33.9
  Top Layer w0.25: U1.9 59,64.95
  Top Layer w0.3: 59,64.95 61.025,66.975
  Top Layer w0.4: 61.025,66.975 61.475,66.975 61.5,67
  Top Layer w0.5: 61.5,67 61.75,67
  Top Layer w0.75: 61.75,67 62.25,67
  Top Layer w1: 62.25,67 76.75,67 78.401,65.349 C4.1 ; C11.2 FB1.1 78.451,54.926 FB1.1@78.7,55.175 ; C11.2 C4.1
MCU-WKUP: C2.1 R3.1 SW22.1 U1.10 | length 54.1
  Top Layer w0.25: U1.10 58,65.45
  Top Layer w0.3: 58,65.45 59.25,66.7
  Top Layer w0.5: 59.25,66.7 59.75,67.2 v1(59.75,67.25) ; C2.1 92.5,57.7 93.9,59.1 95.995,59.1 SW22.1 97.345,59.095 98,59.75 98,61.25 97.357,61.893 96.082,61.893 95.987,61.988 93.513,61.988 v1(93.5,62)
  Bottom Layer w0.5: v1(59.75,67.25) 88.25,67.25 v1(93.5,62)
MCU_BOOT0: R1.1 U1.44 | length 2.2
  Top Layer w0.25: R1.1@53.55,57.725 U1.44
  Top Layer w0.3: R1.1@53.55,57.725 R1.1
NetD1_1: D1.1 Q1.1 R6.2 | length 7.7
  Top Layer w0.5: 63.75,27 63.75,26.461 63.761,26.45 D1.1 ; 63.75,30.5 63.757,30.507 Q1.1@63.757,31.5
  Top Layer w0.75: 63.75,27 63.75,27.5 ; 63.75,30 63.75,30.5
  Top Layer w1: R6.2 61.275,31.5 Q1.1@63.757,31.5 ; 63.75,27.5 63.75,30
NetD2_2: D2.2 R5.2 | length 1.9
  Top Layer w1: R5.2 D2.2
NetJ1_1: J1.1 JP1.1 Q1.3 | length 14.2
  Top Layer w0.5: Q1.3 64.75,34.5
  Top Layer w0.75: 64.75,34.5 64.75,35
  Top Layer w1: J1.1 64.366,36.7 64.666,37 JP1.1 64.75,35
NetP2_11: P2.11 R7.2 | length 5.9
  Top Layer w0.3: R7.2 59.225,41.158 58.88,41.503 58.88,43.34 P2.11
NetP2_17: P2.17 R8.2 | length 8.2
  Top Layer w0.3: P2.17 53.66,43.34 55.357,43.34 56.261,42.436 56.261,41.582 57.025,40.818 R8.2
NetP2_19: P2.19 R9.2 | length 6.1
  Top Layer w0.3: P2.19 51.12,43.34 51.12,41.503 50.25,40.633 R9.2
NetSW1_4: SW1.4 SW5.3 | length 10.7
  Bottom Layer w0.3: SW5.3 53.813,97.063 53.813,98.563 SW1.4
NetSW2_4: SW2.4 SW6.3 | length 10.7
  Bottom Layer w0.3: SW6.3 63.813,97.063 63.813,98.563 SW2.4
NetSW3_4: SW3.4 SW7.3 | length 10.7
  Bottom Layer w0.3: SW7.3 73.813,97.063 73.813,98.563 SW3.4
NetSW4_4: SW4.4 SW8.3 | length 10.7
  Bottom Layer w0.3: SW8.3 83.813,97.063 83.813,98.563 SW4.4
NetSW5_4: SW5.4 SW9.3 | length 10.7
  Bottom Layer w0.3: SW9.3 53.813,89.063 53.813,90.563 SW5.4
NetSW6_4: SW6.4 SW10.3 | length 10.7
  Bottom Layer w0.3: SW10.3 63.813,89.063 63.813,90.563 SW6.4
NetSW7_4: SW7.4 SW11.3 | length 10.7
  Bottom Layer w0.3: SW11.3 73.813,89.063 73.813,90.563 SW7.4
NetSW8_4: SW8.4 SW12.3 | length 10.7
  Bottom Layer w0.3: SW12.3 83.813,89.063 83.813,90.563 SW8.4
NetSW9_4: SW9.4 SW13.3 | length 10.7
  Bottom Layer w0.3: SW13.3 53.813,81.063 53.813,82.563 SW9.4
NetSW10_4: SW10.4 SW14.3 | length 10.7
  Bottom Layer w0.3: SW14.3 63.813,81.063 63.813,82.563 SW10.4
NetSW11_4: SW11.4 SW15.3 | length 10.7
  Bottom Layer w0.3: SW15.3 73.813,81.063 73.813,82.563 SW11.4
NetSW12_4: SW12.4 SW16.3 | length 10.7
  Bottom Layer w0.3: SW16.3 83.813,81.063 83.813,82.563 SW12.4
NetSW13_4: SW13.4 SW17.3 | length 10.7
  Bottom Layer w0.3: SW17.3 53.813,73.063 53.813,74.563 SW13.4
NetSW14_4: SW14.4 SW18.3 | length 10.7
  Bottom Layer w0.3: SW18.3 63.813,73.063 63.813,74.563 SW14.4
NetSW15_4: SW15.4 SW19.3 | length 10.7
  Bottom Layer w0.3: SW19.3 73.813,73.063 73.813,74.563 SW15.4
NetSW16_4: SW16.4 SW20.3 | length 10.7
  Bottom Layer w0.3: SW20.3 83.813,73.063 83.813,74.563 SW16.4
TCK/SWCLK: P2.9 U1.38 | length 35.4
  Top Layer w0.25: 50.55,58.55 U1.38
  Top Layer w0.3: 46,47.75 46,56.75 47.5,58.25 50.25,58.25 50.55,58.55 ; 46.033,47.717 47.25,46.5 55,46.5 56.5,48 60.5,48 62.62,45.88 P2.9
TDI: P2.5 U1.40 | length 34
  Top Layer w0.25: 51.55,57.8 U1.40
  Top Layer w0.3: 51.55,57.8 51,57.25 49.5,57.25 48.75,56.5 48.75,52.25 49.75,51.25 56,51.25 57.25,50 66.25,50 67.75,48.5 67.75,44.59 P2.5
TDO/SWO: P2.13 U1.37 | length 30.1
  Top Layer w0.25: 49,59.5 50.05,59.5 U1.37
  Top Layer w0.3: 49,59.5 46.75,59.5 45,57.75 45,47.25 46.5,45.75 56.33,45.75 P2.13
TMS/SWDIO: P2.7 U1.39 | length 36.5
  Top Layer w0.25: 51.05,58.05 U1.39
  Top Layer w0.3: 51.05,58.05 50.75,57.75 48.5,57.75 47.25,56.5 47.25,47.95 47.95,47.25 54.886,47.25 56.636,49 62.5,49 65.25,46.25 P2.7@65.25,44.7 ; P2.7@65,44.7 P2.7
TRST: JP2.1 P2.3 U1.41 | length 44.2
  Top Layer w0.25: 52.05,57.55 U1.41
  Top Layer w0.3: 52.05,57.55 51.25,56.75 50.5,56.75 50,56.25 50,52.75 50.5,52.25 57.5,52.25 58.75,51 69.25,51 70.25,50 70.25,47.25 ; P2.3 70.25,44.55 70.25,47.25 ; JP2.1 78.123,44.52 76.393,46.25 71.25,46.25 70.25,47.25
V_in: C12.2 D1.3 JP1.2 Q1.2 U2.3 | length 33.1
  Top Layer w0.5: D1.3 65.74,25.5 65.75,25.51 65.75,26 ; Q1.2 65.716,31.444 65.716,30.534 65.75,30.5
  Top Layer w0.75: 65.75,30 65.75,30.5
  Top Layer w1: 65.75,26 65.75,28.75 ; 65.75,30 65.75,28.75 ; JP1.2 69,37 ; C12.2@73.2,34.75 73.2,36.8 73,37 ; U2.3 74.25,38.25 73,37 ; 65.75,28.75 68.414,28.75 69,29.336 69,37 ; 69,37 73,37
VOUT: C3.2 T1.8 | length 28.8
  Top Layer w0.3: C3.2@49.201,123.4 C3.2
  Top Layer w0.5: v1(47.2,123.4) C3.2@49.201,123.4
  Bottom Layer w0.5: v1(47.2,123.4) 59,123.4 68.05,114.35 T1.8
X_OSC_OUT: C15.1 R4.2 X1.2 | length 12.6
  Top Layer w0.3: R4.2 64.05,59.05 64.5,59.5 64.5,63 65,63.5 X1.2@66,63.5 ; X1.2@66.026,63.026 X1.2 69.6,63.5 C15.1
pads on no net: D1.2 SW1.1 SW1.3 SW2.1 SW2.3 SW3.1 SW3.3 SW4.1 SW4.3 SW5.1 SW6.1 SW7.1 SW8.1 SW9.1 SW10.1 SW11.1 SW12.1 SW13.1 SW14.1 SW15.1 SW16.1 SW17.1 SW18.1 SW19.1 SW20.1 T1.TH U1.2 U1.3 U1.4 U1.11 U1.12 U1.13 U1.30 U1.31 U1.32 U1.33 U1.34 U1.42 U1.43 U1.45 U1.46

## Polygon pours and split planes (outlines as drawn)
GND on Bottom Layer "GND_L02_P001" (solid, remove dead copper, pour order 1): 45,25 ccw(c46.5,25) 46.5,23.5 97.5,23.5 ccw(c97.5,25) 99,25 99,135 ccw(c97.5,135) 97.5,136.5 46.5,136.5 ccw(c46.5,135) 45,135
GND on Top Layer "GND_L01_P002" (solid, remove dead copper, pour order 2): 45,25 ccw(c46.5,25) 46.5,23.5 97.5,23.5 ccw(c97.5,25) 99,25 99,135 ccw(c97.5,135) 97.5,136.5 46.5,136.5 ccw(c46.5,135) 45,135

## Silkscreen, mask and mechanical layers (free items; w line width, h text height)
Top Overlay:
  lines w0.2: 91,46 99,46 99,67 91,67 ; 91,46 83,46 83,67 91,67 ; 91,46 91,67 ; 47.025,58.45 58.4,58.45 58.4,69.2 47.025,69.2 47.025,58.45 ; 91.875,32.425 98,32.425 98,44.525 91.875,44.525 91.875,32.425
  text "Display" at 50.573,131.45 h1.52 r90
  text "Button Matrix Header" at 93.987,82.475 h1.52 r90
  text "Designed by Niklas Chaney" at 47.853,75.2 h3 r90
  text "7/17/2023" at 49.731,75.2 h2 r90
  text "MCU" at 58.675,68.313 h1.52
  text "RST" at 83.1,67.213 h1.52
  text "WKUP" at 91.1,67.213 h1.52
  text "CLOCK" at 64.2,65.993 h1.52
  text "BOOT0" at 47.087,50.1 h1.52 r90
  text "JTAG Header" at 66.08,46.038 h1.52
  text "5V DC" at 49.212,33.772 h1.52 r90
  text "POWER" at 91.662,32.625 h1.52 r90
Mechanical 1:
  the board outline again, w0.2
